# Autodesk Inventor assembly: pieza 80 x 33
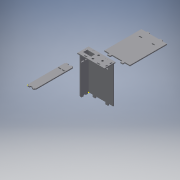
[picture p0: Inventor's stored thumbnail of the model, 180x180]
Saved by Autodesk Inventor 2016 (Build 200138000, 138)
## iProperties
Created: 2016-06
Part Number: pieza 80 x 33
Material: Genérico
Document SubType Name: Assembly
Designer: adm
Author: adm
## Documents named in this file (4)
- C:\Users\adm\Desktop\alvarez soporte de rueda\pieza 80 x 33.iam
- C:\Users\adm\Desktop\Base\Pieza19.ipt
- C:\Users\adm\Desktop\alvarez soporte de rueda\pieza 110 x 30.ipt
- C:\Users\adm\Desktop\alvarez soporte de rueda\pieza 110 x 75.ipt
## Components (5 placed, 3 different names)
1. Pieza19:1 — Nivelación:1, Coincidencia:1, Coincidencia:2, Nivelación:2, Coincidencia:3, Coincidencia:4
2. pieza 110 x 30:1
3. pieza 110 x 30:2 — Nivelación:2, Coincidencia:3, Coincidencia:4
4. pieza 110 x 75:1 — Nivelación:1, Coincidencia:1, Coincidencia:2
5. pieza 110 x 75:2
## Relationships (6: Mate 4, Flush 2)
- Nivelación:1 [Flush]: Pieza19:1 ↔ pieza 110 x 75:1
- Coincidencia:1 [Mate]: Pieza19:1 ↔ pieza 110 x 75:1
- Coincidencia:2 [Mate]: Pieza19:1 ↔ pieza 110 x 75:1
- Nivelación:2 [Flush]: Pieza19:1 ↔ pieza 110 x 30:2
- Coincidencia:3 [Mate]: Pieza19:1 ↔ pieza 110 x 30:2
- Coincidencia:4 [Mate]: Pieza19:1 ↔ pieza 110 x 30:2
